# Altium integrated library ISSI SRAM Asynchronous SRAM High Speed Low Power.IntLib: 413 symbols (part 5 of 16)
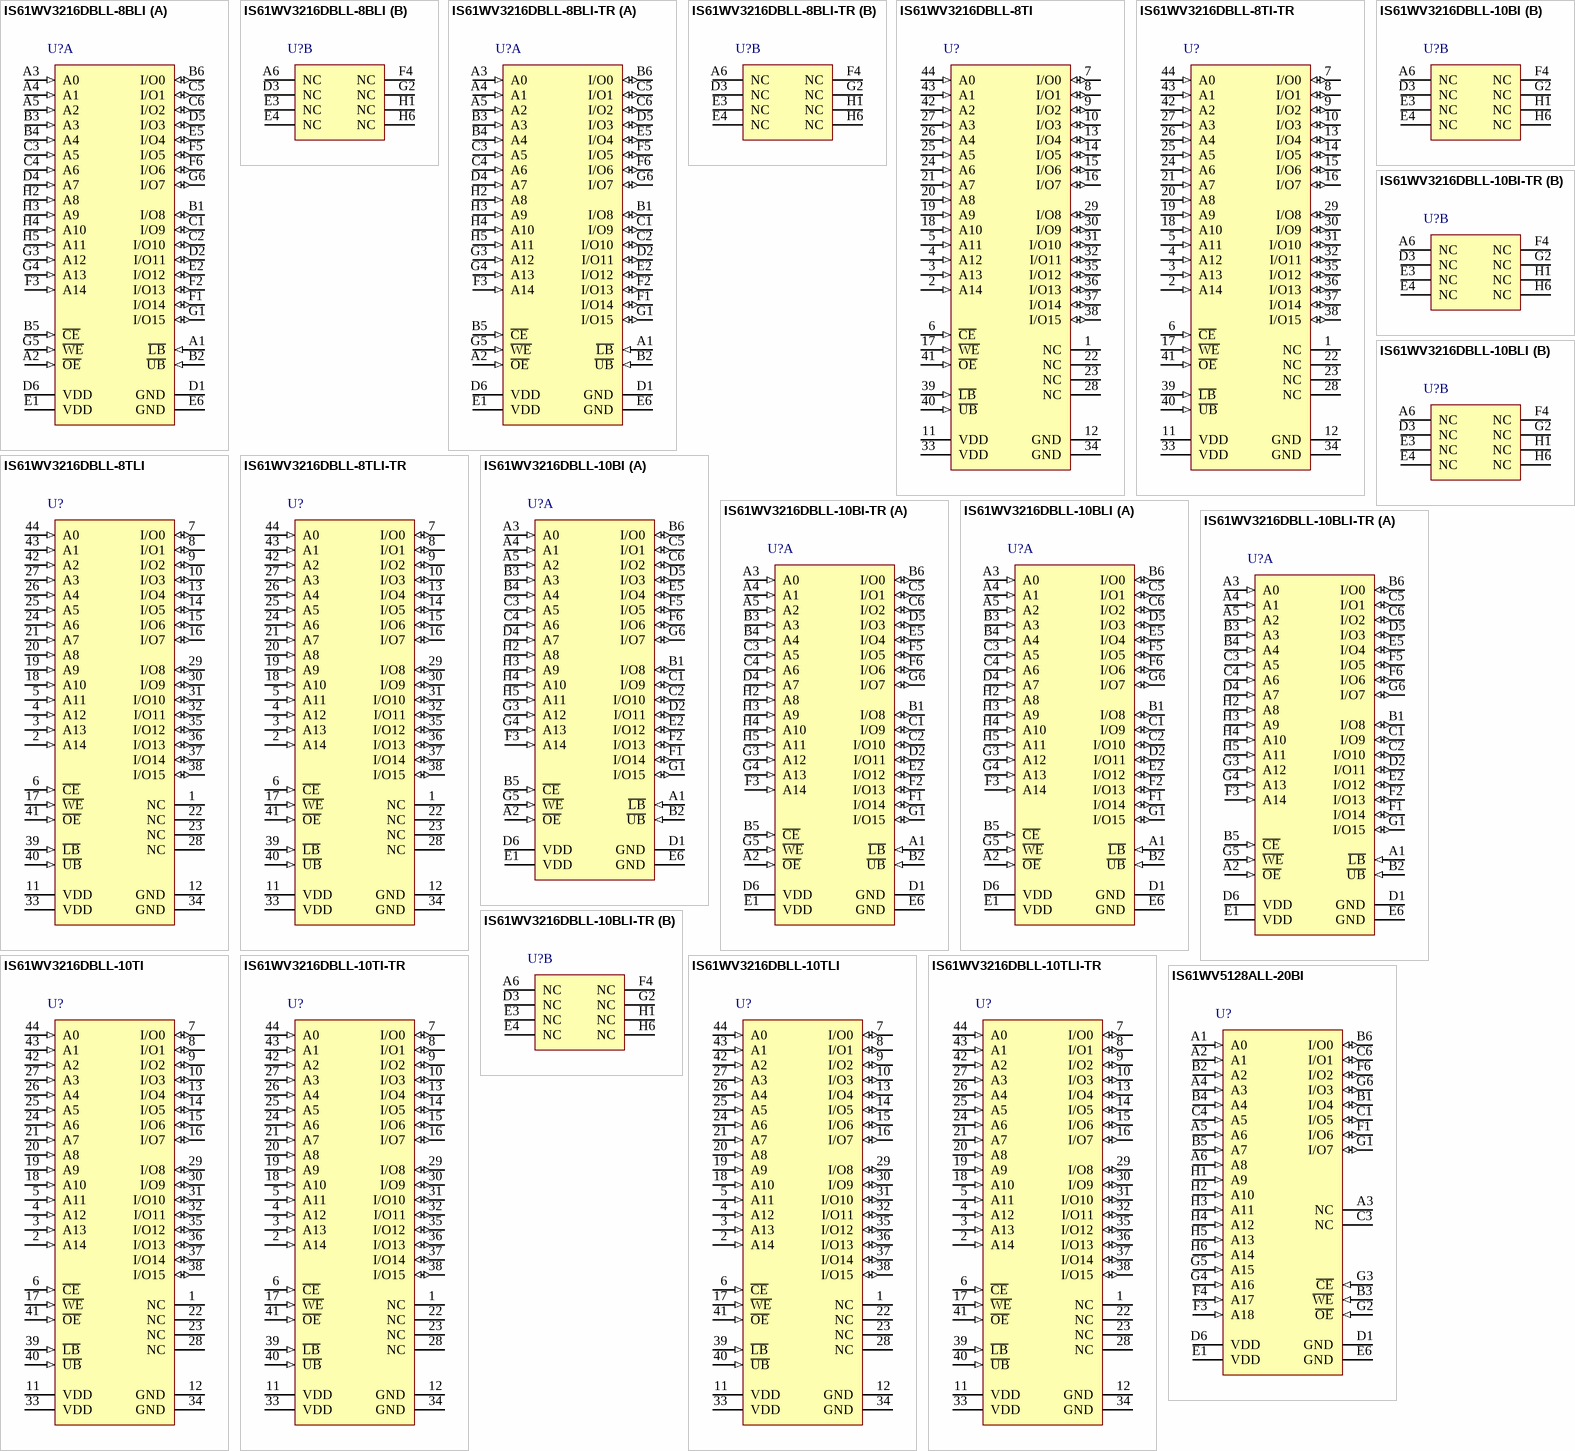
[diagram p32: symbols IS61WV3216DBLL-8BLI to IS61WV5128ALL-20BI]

## IS61WV3216DBLL-10TLI
designator U?
512 K High Speed Asynchronous CMOS SRAM, 32 K x 16, -40 to 85 degC, 44-Pin SOP (TSOP-2-44), Pb-Free; Manufacturer: Integrated Silicon Solution Inc (ISSI); PartNumber: IS61WV3216DBLL-10TLI; Density: 512K; Organization: 32K x 16; Packing: Tray / Tube; Speed (ns): 10
footprint ISSI-TSOP-2-44_N (SOP, 44-Leads, Body 18.5x10.3mm, Pitch 0.8mm, IPC Medium Density)
pins: 1 NC "No Connection", 2 A14 (in) "Address Input", 3 A13 (in) "Address Input", 4 A12 (in) "Address Input", 5 A11 (in) "Address Input", 6 ~{CE} (in) "Chip Enable Input", 7 I/O0 (io) "Data Input/Output", 8 I/O1 (io) "Data Input/Output", 9 I/O2 (io) "Data Input/Output", 10 I/O3 (io) "Data Input/Output", 11 VDD (power) "Power", 12 GND (power) "Ground", 13 I/O4 (io) "Data Input/Output", 14 I/O5 (io) "Data Input/Output", 15 I/O6 (io) "Data Input/Output", 16 I/O7 (io) "Data Input/Output", 17 ~{WE} (in) "Write Enable Input", 18 A10 (in) "Address Input", 19 A9 (in) "Address Input", 20 A8 (in) "Address Input", 21 A7 (in) "Address Input", 22 NC "No Connection", 23 NC "No Connection", 24 A6 (in) "Address Input", 25 A5 (in) "Address Input", 26 A4 (in) "Address Input", 27 A3 (in) "Address Input", 28 NC "No Connection", 29 I/O8 (io) "Data Input/Output", 30 I/O9 (io) "Data Input/Output", 31 I/O10 (io) "Data Input/Output", 32 I/O11 (io) "Data Input/Output", 33 VDD (power) "Power", 34 GND (power) "Ground", 35 I/O12 (io) "Data Input/Output", 36 I/O13 (io) "Data Input/Output", 37 I/O14 (io) "Data Input/Output", 38 I/O15 (io) "Data Input/Output", 39 ~{LB} (in) "Lower-byte Control (I/O0-I/O7)", 40 ~{UB} (in) "Upper-byte Control (I/O8-I/O15)", 41 ~{OE} (in) "Output Enable Input", 42 A2 (in) "Address Input", 43 A1 (in) "Address Input", 44 A0 (in) "Address Input"

## IS61WV3216DBLL-10TLI-TR
designator U?
512 K High Speed Asynchronous CMOS SRAM, 32 K x 16, -40 to 85 degC, 44-Pin SOP (TSOP-2-44), Pb-Free; Manufacturer: Integrated Silicon Solution Inc (ISSI); PartNumber: IS61WV3216DBLL-10TLI-TR; Density: 512K; Organization: 32K x 16; Packing: Tape & Reel; Speed (ns): 10
footprint ISSI-TSOP-2-44_N (SOP, 44-Leads, Body 18.5x10.3mm, Pitch 0.8mm, IPC Medium Density)
pins: 1 NC "No Connection", 2 A14 (in) "Address Input", 3 A13 (in) "Address Input", 4 A12 (in) "Address Input", 5 A11 (in) "Address Input", 6 ~{CE} (in) "Chip Enable Input", 7 I/O0 (io) "Data Input/Output", 8 I/O1 (io) "Data Input/Output", 9 I/O2 (io) "Data Input/Output", 10 I/O3 (io) "Data Input/Output", 11 VDD (power) "Power", 12 GND (power) "Ground", 13 I/O4 (io) "Data Input/Output", 14 I/O5 (io) "Data Input/Output", 15 I/O6 (io) "Data Input/Output", 16 I/O7 (io) "Data Input/Output", 17 ~{WE} (in) "Write Enable Input", 18 A10 (in) "Address Input", 19 A9 (in) "Address Input", 20 A8 (in) "Address Input", 21 A7 (in) "Address Input", 22 NC "No Connection", 23 NC "No Connection", 24 A6 (in) "Address Input", 25 A5 (in) "Address Input", 26 A4 (in) "Address Input", 27 A3 (in) "Address Input", 28 NC "No Connection", 29 I/O8 (io) "Data Input/Output", 30 I/O9 (io) "Data Input/Output", 31 I/O10 (io) "Data Input/Output", 32 I/O11 (io) "Data Input/Output", 33 VDD (power) "Power", 34 GND (power) "Ground", 35 I/O12 (io) "Data Input/Output", 36 I/O13 (io) "Data Input/Output", 37 I/O14 (io) "Data Input/Output", 38 I/O15 (io) "Data Input/Output", 39 ~{LB} (in) "Lower-byte Control (I/O0-I/O7)", 40 ~{UB} (in) "Upper-byte Control (I/O8-I/O15)", 41 ~{OE} (in) "Output Enable Input", 42 A2 (in) "Address Input", 43 A1 (in) "Address Input", 44 A0 (in) "Address Input"

## IS61WV5128ALL-20BI
designator U?
4 M High Speed Asynchronous CMOS SRAM, 512 K x 8, -40 to 85 degC, 36-Pin BGA (TF-BGA-36); Manufacturer: Integrated Silicon Solution Inc (ISSI); PartNumber: IS61WV5128ALL-20BI; Density: 4M; Organization: 512K x 8; Packing: Tray / Tube; Speed (ns): 20
footprint ISSI-TF-BGA-36-6000x8000DE (BGA, 36-Balls, Body 8x6mm, Pitch 0.75mm)
pins: A1 A0 (in) "Address Input", A2 A1 (in) "Address Input", A3 NC "No Connection", A4 A3 (in) "Address Input", A5 A6 (in) "Address Input", A6 A8 (in) "Address Input", B1 I/O4 (io) "Bidirectional Port", B2 A2 (in) "Address Input", B3 ~{WE} (in) "Write Enable Input", B4 A4 (in) "Address Input", B5 A7 (in) "Address Input", B6 I/O0 (io) "Bidirectional Port", C1 I/O5 (io) "Bidirectional Port", C3 NC "No Connection", C4 A5 (in) "Address Input", C6 I/O1 (io) "Bidirectional Port", D1 GND (power) "Ground", D6 VDD (power) "Power", E1 VDD (power) "Power", E6 GND (power) "Ground", F1 I/O6 (io) "Bidirectional Port", F3 A18 (in) "Address Input", F4 A17 (in) "Address Input", F6 I/O2 (io) "Bidirectional Port", G1 I/O7 (io) "Bidirectional Port", G2 ~{OE} (in) "Output Enable Input", G3 ~{CE} (in) "Chip Enable Input", G4 A16 (in) "Address Input", G5 A15 (in) "Address Input", G6 I/O3 (io) "Bidirectional Port", H1 A9 (in) "Address Input", H2 A10 (in) "Address Input", H3 A11 (in) "Address Input", H4 A12 (in) "Address Input", H5 A13 (in) "Address Input", H6 A14 (in) "Address Input"

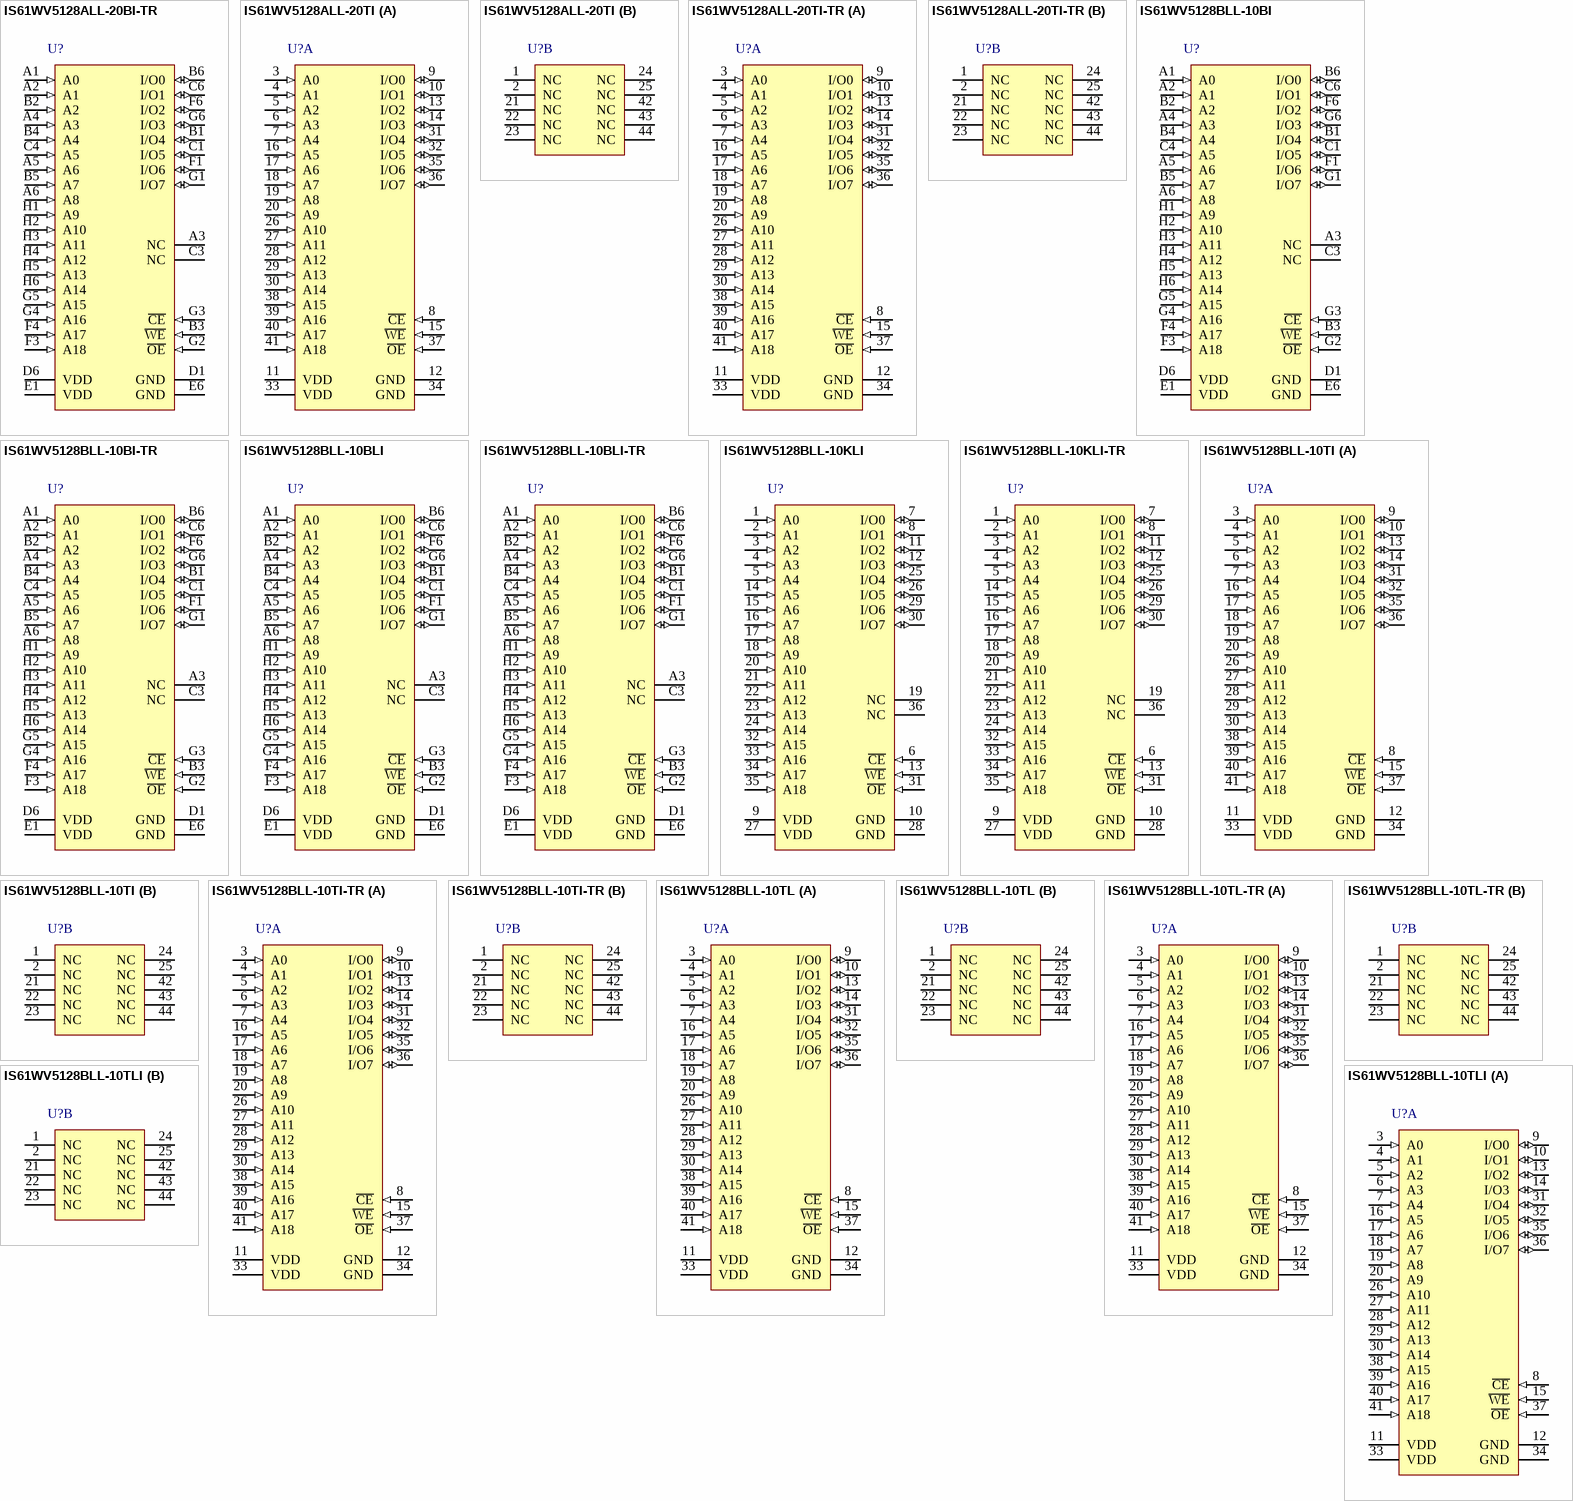
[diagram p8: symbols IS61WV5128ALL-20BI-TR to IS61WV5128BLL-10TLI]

## IS61WV5128ALL-20BI-TR
designator U?
4 M High Speed Asynchronous CMOS SRAM, 512 K x 8, -40 to 85 degC, 36-Pin BGA (TF-BGA-36); Manufacturer: Integrated Silicon Solution Inc (ISSI); PartNumber: IS61WV5128ALL-20BI-TR; Density: 4M; Organization: 512K x 8; Packing: Tape & Reel; Speed (ns): 20
footprint ISSI-TF-BGA-36-6000x8000DE (BGA, 36-Balls, Body 8x6mm, Pitch 0.75mm)
pins: A1 A0 (in) "Address Input", A2 A1 (in) "Address Input", A3 NC "No Connection", A4 A3 (in) "Address Input", A5 A6 (in) "Address Input", A6 A8 (in) "Address Input", B1 I/O4 (io) "Bidirectional Port", B2 A2 (in) "Address Input", B3 ~{WE} (in) "Write Enable Input", B4 A4 (in) "Address Input", B5 A7 (in) "Address Input", B6 I/O0 (io) "Bidirectional Port", C1 I/O5 (io) "Bidirectional Port", C3 NC "No Connection", C4 A5 (in) "Address Input", C6 I/O1 (io) "Bidirectional Port", D1 GND (power) "Ground", D6 VDD (power) "Power", E1 VDD (power) "Power", E6 GND (power) "Ground", F1 I/O6 (io) "Bidirectional Port", F3 A18 (in) "Address Input", F4 A17 (in) "Address Input", F6 I/O2 (io) "Bidirectional Port", G1 I/O7 (io) "Bidirectional Port", G2 ~{OE} (in) "Output Enable Input", G3 ~{CE} (in) "Chip Enable Input", G4 A16 (in) "Address Input", G5 A15 (in) "Address Input", G6 I/O3 (io) "Bidirectional Port", H1 A9 (in) "Address Input", H2 A10 (in) "Address Input", H3 A11 (in) "Address Input", H4 A12 (in) "Address Input", H5 A13 (in) "Address Input", H6 A14 (in) "Address Input"

## IS61WV5128ALL-20TI
designator U?
4 M High Speed Asynchronous CMOS SRAM, 512 K x 8, -40 to 85 degC, 44-Pin SOP (TSOP-2-44); Manufacturer: Integrated Silicon Solution Inc (ISSI); PartNumber: IS61WV5128ALL-20TI; Density: 4M; Organization: 512K x 8; Packing: Tray / Tube; Speed (ns): 20
footprint ISSI-TSOP-2-44_N (SOP, 44-Leads, Body 18.5x10.3mm, Pitch 0.8mm, IPC Medium Density)
part A pins: 3 A0 (in) "Address Input", 4 A1 (in) "Address Input", 5 A2 (in) "Address Input", 6 A3 (in) "Address Input", 7 A4 (in) "Address Input", 8 ~{CE} (in) "Chip Enable Input", 9 I/O0 (io) "Bidirectional Port", 10 I/O1 (io) "Bidirectional Port", 11 VDD (power) "Power", 12 GND (power) "Ground", 13 I/O2 (io) "Bidirectional Port", 14 I/O3 (io) "Bidirectional Port", 15 ~{WE} (in) "Write Enable Input", 16 A5 (in) "Address Input", 17 A6 (in) "Address Input", 18 A7 (in) "Address Input", 19 A8 (in) "Address Input", 20 A9 (in) "Address Input", 26 A10 (in) "Address Input", 27 A11 (in) "Address Input", 28 A12 (in) "Address Input", 29 A13 (in) "Address Input", 30 A14 (in) "Address Input", 31 I/O4 (io) "Bidirectional Port", 32 I/O5 (io) "Bidirectional Port", 33 VDD (power) "Power", 34 GND (power) "Ground", 35 I/O6 (io) "Bidirectional Port", 36 I/O7 (io) "Bidirectional Port", 37 ~{OE} (in) "Output Enable Input", 38 A15 (in) "Address Input", 39 A16 (in) "Address Input", 40 A17 (in) "Address Input", 41 A18 (in) "Address Input"
part B pins: 1 NC "No Connection", 2 NC "No Connection", 21 NC "No Connection", 22 NC "No Connection", 23 NC "No Connection", 24 NC "No Connection", 25 NC "No Connection", 42 NC "No Connection", 43 NC "No Connection", 44 NC "No Connection"

## IS61WV5128ALL-20TI-TR
designator U?
4 M High Speed Asynchronous CMOS SRAM, 512 K x 8, -40 to 85 degC, 44-Pin SOP (TSOP-2-44); Manufacturer: Integrated Silicon Solution Inc (ISSI); PartNumber: IS61WV5128ALL-20TI-TR; Density: 4M; Organization: 512K x 8; Packing: Tape & Reel; Speed (ns): 20
footprint ISSI-TSOP-2-44_N (SOP, 44-Leads, Body 18.5x10.3mm, Pitch 0.8mm, IPC Medium Density)
part A pins: 3 A0 (in) "Address Input", 4 A1 (in) "Address Input", 5 A2 (in) "Address Input", 6 A3 (in) "Address Input", 7 A4 (in) "Address Input", 8 ~{CE} (in) "Chip Enable Input", 9 I/O0 (io) "Bidirectional Port", 10 I/O1 (io) "Bidirectional Port", 11 VDD (power) "Power", 12 GND (power) "Ground", 13 I/O2 (io) "Bidirectional Port", 14 I/O3 (io) "Bidirectional Port", 15 ~{WE} (in) "Write Enable Input", 16 A5 (in) "Address Input", 17 A6 (in) "Address Input", 18 A7 (in) "Address Input", 19 A8 (in) "Address Input", 20 A9 (in) "Address Input", 26 A10 (in) "Address Input", 27 A11 (in) "Address Input", 28 A12 (in) "Address Input", 29 A13 (in) "Address Input", 30 A14 (in) "Address Input", 31 I/O4 (io) "Bidirectional Port", 32 I/O5 (io) "Bidirectional Port", 33 VDD (power) "Power", 34 GND (power) "Ground", 35 I/O6 (io) "Bidirectional Port", 36 I/O7 (io) "Bidirectional Port", 37 ~{OE} (in) "Output Enable Input", 38 A15 (in) "Address Input", 39 A16 (in) "Address Input", 40 A17 (in) "Address Input", 41 A18 (in) "Address Input"
part B pins: 1 NC "No Connection", 2 NC "No Connection", 21 NC "No Connection", 22 NC "No Connection", 23 NC "No Connection", 24 NC "No Connection", 25 NC "No Connection", 42 NC "No Connection", 43 NC "No Connection", 44 NC "No Connection"

## IS61WV5128BLL-10BI
designator U?
4 M High Speed Asynchronous CMOS SRAM, 512 K x 8, -40 to 85 degC, 36-Pin BGA (TF-BGA-36); Manufacturer: Integrated Silicon Solution Inc (ISSI); PartNumber: IS61WV5128BLL-10BI; Density: 4M; Organization: 512K x 8; Packing: Tray / Tube; Speed (ns): 10
footprint ISSI-TF-BGA-36-6000x8000DE (BGA, 36-Balls, Body 8x6mm, Pitch 0.75mm)
pins: A1 A0 (in) "Address Input", A2 A1 (in) "Address Input", A3 NC "No Connection", A4 A3 (in) "Address Input", A5 A6 (in) "Address Input", A6 A8 (in) "Address Input", B1 I/O4 (io) "Bidirectional Port", B2 A2 (in) "Address Input", B3 ~{WE} (in) "Write Enable Input", B4 A4 (in) "Address Input", B5 A7 (in) "Address Input", B6 I/O0 (io) "Bidirectional Port", C1 I/O5 (io) "Bidirectional Port", C3 NC "No Connection", C4 A5 (in) "Address Input", C6 I/O1 (io) "Bidirectional Port", D1 GND (power) "Ground", D6 VDD (power) "Power", E1 VDD (power) "Power", E6 GND (power) "Ground", F1 I/O6 (io) "Bidirectional Port", F3 A18 (in) "Address Input", F4 A17 (in) "Address Input", F6 I/O2 (io) "Bidirectional Port", G1 I/O7 (io) "Bidirectional Port", G2 ~{OE} (in) "Output Enable Input", G3 ~{CE} (in) "Chip Enable Input", G4 A16 (in) "Address Input", G5 A15 (in) "Address Input", G6 I/O3 (io) "Bidirectional Port", H1 A9 (in) "Address Input", H2 A10 (in) "Address Input", H3 A11 (in) "Address Input", H4 A12 (in) "Address Input", H5 A13 (in) "Address Input", H6 A14 (in) "Address Input"

## IS61WV5128BLL-10BI-TR
designator U?
4 M High Speed Asynchronous CMOS SRAM, 512 K x 8, -40 to 85 degC, 36-Pin BGA (TF-BGA-36); Manufacturer: Integrated Silicon Solution Inc (ISSI); PartNumber: IS61WV5128BLL-10BI-TR; Density: 4M; Organization: 512K x 8; Packing: Tape & Reel; Speed (ns): 10
footprint ISSI-TF-BGA-36-6000x8000DE (BGA, 36-Balls, Body 8x6mm, Pitch 0.75mm)
pins: A1 A0 (in) "Address Input", A2 A1 (in) "Address Input", A3 NC "No Connection", A4 A3 (in) "Address Input", A5 A6 (in) "Address Input", A6 A8 (in) "Address Input", B1 I/O4 (io) "Bidirectional Port", B2 A2 (in) "Address Input", B3 ~{WE} (in) "Write Enable Input", B4 A4 (in) "Address Input", B5 A7 (in) "Address Input", B6 I/O0 (io) "Bidirectional Port", C1 I/O5 (io) "Bidirectional Port", C3 NC "No Connection", C4 A5 (in) "Address Input", C6 I/O1 (io) "Bidirectional Port", D1 GND (power) "Ground", D6 VDD (power) "Power", E1 VDD (power) "Power", E6 GND (power) "Ground", F1 I/O6 (io) "Bidirectional Port", F3 A18 (in) "Address Input", F4 A17 (in) "Address Input", F6 I/O2 (io) "Bidirectional Port", G1 I/O7 (io) "Bidirectional Port", G2 ~{OE} (in) "Output Enable Input", G3 ~{CE} (in) "Chip Enable Input", G4 A16 (in) "Address Input", G5 A15 (in) "Address Input", G6 I/O3 (io) "Bidirectional Port", H1 A9 (in) "Address Input", H2 A10 (in) "Address Input", H3 A11 (in) "Address Input", H4 A12 (in) "Address Input", H5 A13 (in) "Address Input", H6 A14 (in) "Address Input"

## IS61WV5128BLL-10BLI
designator U?
4 M High Speed Asynchronous CMOS SRAM, 512 K x 8, -40 to 85 degC, 36-Pin BGA (TF-BGA-36), Pb-Free; Manufacturer: Integrated Silicon Solution Inc (ISSI); PartNumber: IS61WV5128BLL-10BLI; Density: 4M; Organization: 512K x 8; Packing: Tray / Tube; Speed (ns): 10
footprint ISSI-TF-BGA-36-6000x8000DE (BGA, 36-Balls, Body 8x6mm, Pitch 0.75mm)
pins: A1 A0 (in) "Address Input", A2 A1 (in) "Address Input", A3 NC "No Connection", A4 A3 (in) "Address Input", A5 A6 (in) "Address Input", A6 A8 (in) "Address Input", B1 I/O4 (io) "Bidirectional Port", B2 A2 (in) "Address Input", B3 ~{WE} (in) "Write Enable Input", B4 A4 (in) "Address Input", B5 A7 (in) "Address Input", B6 I/O0 (io) "Bidirectional Port", C1 I/O5 (io) "Bidirectional Port", C3 NC "No Connection", C4 A5 (in) "Address Input", C6 I/O1 (io) "Bidirectional Port", D1 GND (power) "Ground", D6 VDD (power) "Power", E1 VDD (power) "Power", E6 GND (power) "Ground", F1 I/O6 (io) "Bidirectional Port", F3 A18 (in) "Address Input", F4 A17 (in) "Address Input", F6 I/O2 (io) "Bidirectional Port", G1 I/O7 (io) "Bidirectional Port", G2 ~{OE} (in) "Output Enable Input", G3 ~{CE} (in) "Chip Enable Input", G4 A16 (in) "Address Input", G5 A15 (in) "Address Input", G6 I/O3 (io) "Bidirectional Port", H1 A9 (in) "Address Input", H2 A10 (in) "Address Input", H3 A11 (in) "Address Input", H4 A12 (in) "Address Input", H5 A13 (in) "Address Input", H6 A14 (in) "Address Input"

## IS61WV5128BLL-10BLI-TR
designator U?
4 M High Speed Asynchronous CMOS SRAM, 512 K x 8, -40 to 85 degC, 36-Pin BGA (TF-BGA-36), Pb-Free; Manufacturer: Integrated Silicon Solution Inc (ISSI); PartNumber: IS61WV5128BLL-10BLI-TR; Density: 4M; Organization: 512K x 8; Packing: Tape & Reel; Speed (ns): 10
footprint ISSI-TF-BGA-36-6000x8000DE (BGA, 36-Balls, Body 8x6mm, Pitch 0.75mm)
pins: A1 A0 (in) "Address Input", A2 A1 (in) "Address Input", A3 NC "No Connection", A4 A3 (in) "Address Input", A5 A6 (in) "Address Input", A6 A8 (in) "Address Input", B1 I/O4 (io) "Bidirectional Port", B2 A2 (in) "Address Input", B3 ~{WE} (in) "Write Enable Input", B4 A4 (in) "Address Input", B5 A7 (in) "Address Input", B6 I/O0 (io) "Bidirectional Port", C1 I/O5 (io) "Bidirectional Port", C3 NC "No Connection", C4 A5 (in) "Address Input", C6 I/O1 (io) "Bidirectional Port", D1 GND (power) "Ground", D6 VDD (power) "Power", E1 VDD (power) "Power", E6 GND (power) "Ground", F1 I/O6 (io) "Bidirectional Port", F3 A18 (in) "Address Input", F4 A17 (in) "Address Input", F6 I/O2 (io) "Bidirectional Port", G1 I/O7 (io) "Bidirectional Port", G2 ~{OE} (in) "Output Enable Input", G3 ~{CE} (in) "Chip Enable Input", G4 A16 (in) "Address Input", G5 A15 (in) "Address Input", G6 I/O3 (io) "Bidirectional Port", H1 A9 (in) "Address Input", H2 A10 (in) "Address Input", H3 A11 (in) "Address Input", H4 A12 (in) "Address Input", H5 A13 (in) "Address Input", H6 A14 (in) "Address Input"

## IS61WV5128BLL-10KLI
designator U?
4 M High Speed Asynchronous CMOS SRAM, 512 K x 8, -40 to 85 degC, 36-Pin SOJ (SOJ-36), Pb-Free; Manufacturer: Integrated Silicon Solution Inc (ISSI); PartNumber: IS61WV5128BLL-10KLI; Density: 4M; Organization: 512K x 8; Packing: Tray / Tube; Speed (ns): 10
footprint ISSI-SOJ-36_N (SOJ, 36-Leads, Body 23.62x10.29mm, Pitch 1.27mm, IPC Medium Density)
pins: 1 A0 (in) "Address Input", 2 A1 (in) "Address Input", 3 A2 (in) "Address Input", 4 A3 (in) "Address Input", 5 A4 (in) "Address Input", 6 ~{CE} (in) "Chip Enable Input", 7 I/O0 (io) "Bidirectional Port", 8 I/O1 (io) "Bidirectional Port", 9 VDD (power) "Power", 10 GND (power) "Ground", 11 I/O2 (io) "Bidirectional Port", 12 I/O3 (io) "Bidirectional Port", 13 ~{WE} (in) "Write Enable Input", 14 A5 (in) "Address Input", 15 A6 (in) "Address Input", 16 A7 (in) "Address Input", 17 A8 (in) "Address Input", 18 A9 (in) "Address Input", 19 NC "No Connection", 20 A10 (in) "Address Input", 21 A11 (in) "Address Input", 22 A12 (in) "Address Input", 23 A13 (in) "Address Input", 24 A14 (in) "Address Input", 25 I/O4 (io) "Bidirectional Port", 26 I/O5 (io) "Bidirectional Port", 27 VDD (power) "Power", 28 GND (power) "Ground", 29 I/O6 (io) "Bidirectional Port", 30 I/O7 (io) "Bidirectional Port", 31 ~{OE} (in) "Output Enable Input", 32 A15 (in) "Address Input", 33 A16 (in) "Address Input", 34 A17 (in) "Address Input", 35 A18 (in) "Address Input", 36 NC "No Connection"

## IS61WV5128BLL-10KLI-TR
designator U?
4 M High Speed Asynchronous CMOS SRAM, 512 K x 8, -40 to 85 degC, 36-Pin SOJ (SOJ-36), Pb-Free; Manufacturer: Integrated Silicon Solution Inc (ISSI); PartNumber: IS61WV5128BLL-10KLI-TR; Density: 4M; Organization: 512K x 8; Packing: Tape & Reel; Speed (ns): 10
footprint ISSI-SOJ-36_N (SOJ, 36-Leads, Body 23.62x10.29mm, Pitch 1.27mm, IPC Medium Density)
pins: 1 A0 (in) "Address Input", 2 A1 (in) "Address Input", 3 A2 (in) "Address Input", 4 A3 (in) "Address Input", 5 A4 (in) "Address Input", 6 ~{CE} (in) "Chip Enable Input", 7 I/O0 (io) "Bidirectional Port", 8 I/O1 (io) "Bidirectional Port", 9 VDD (power) "Power", 10 GND (power) "Ground", 11 I/O2 (io) "Bidirectional Port", 12 I/O3 (io) "Bidirectional Port", 13 ~{WE} (in) "Write Enable Input", 14 A5 (in) "Address Input", 15 A6 (in) "Address Input", 16 A7 (in) "Address Input", 17 A8 (in) "Address Input", 18 A9 (in) "Address Input", 19 NC "No Connection", 20 A10 (in) "Address Input", 21 A11 (in) "Address Input", 22 A12 (in) "Address Input", 23 A13 (in) "Address Input", 24 A14 (in) "Address Input", 25 I/O4 (io) "Bidirectional Port", 26 I/O5 (io) "Bidirectional Port", 27 VDD (power) "Power", 28 GND (power) "Ground", 29 I/O6 (io) "Bidirectional Port", 30 I/O7 (io) "Bidirectional Port", 31 ~{OE} (in) "Output Enable Input", 32 A15 (in) "Address Input", 33 A16 (in) "Address Input", 34 A17 (in) "Address Input", 35 A18 (in) "Address Input", 36 NC "No Connection"

## IS61WV5128BLL-10TI
designator U?
4 M High Speed Asynchronous CMOS SRAM, 512 K x 8, -40 to 85 degC, 44-Pin SOP (TSOP-2-44); Manufacturer: Integrated Silicon Solution Inc (ISSI); PartNumber: IS61WV5128BLL-10TI; Density: 4M; Organization: 512K x 8; Packing: Tray / Tube; Speed (ns): 10
footprint ISSI-TSOP-2-44_N (SOP, 44-Leads, Body 18.5x10.3mm, Pitch 0.8mm, IPC Medium Density)
part A pins: 3 A0 (in) "Address Input", 4 A1 (in) "Address Input", 5 A2 (in) "Address Input", 6 A3 (in) "Address Input", 7 A4 (in) "Address Input", 8 ~{CE} (in) "Chip Enable Input", 9 I/O0 (io) "Bidirectional Port", 10 I/O1 (io) "Bidirectional Port", 11 VDD (power) "Power", 12 GND (power) "Ground", 13 I/O2 (io) "Bidirectional Port", 14 I/O3 (io) "Bidirectional Port", 15 ~{WE} (in) "Write Enable Input", 16 A5 (in) "Address Input", 17 A6 (in) "Address Input", 18 A7 (in) "Address Input", 19 A8 (in) "Address Input", 20 A9 (in) "Address Input", 26 A10 (in) "Address Input", 27 A11 (in) "Address Input", 28 A12 (in) "Address Input", 29 A13 (in) "Address Input", 30 A14 (in) "Address Input", 31 I/O4 (io) "Bidirectional Port", 32 I/O5 (io) "Bidirectional Port", 33 VDD (power) "Power", 34 GND (power) "Ground", 35 I/O6 (io) "Bidirectional Port", 36 I/O7 (io) "Bidirectional Port", 37 ~{OE} (in) "Output Enable Input", 38 A15 (in) "Address Input", 39 A16 (in) "Address Input", 40 A17 (in) "Address Input", 41 A18 (in) "Address Input"
part B pins: 1 NC "No Connection", 2 NC "No Connection", 21 NC "No Connection", 22 NC "No Connection", 23 NC "No Connection", 24 NC "No Connection", 25 NC "No Connection", 42 NC "No Connection", 43 NC "No Connection", 44 NC "No Connection"

## IS61WV5128BLL-10TI-TR
designator U?
4 M High Speed Asynchronous CMOS SRAM, 512 K x 8, -40 to 85 degC, 44-Pin SOP (TSOP-2-44); Manufacturer: Integrated Silicon Solution Inc (ISSI); PartNumber: IS61WV5128BLL-10TI-TR; Density: 4M; Organization: 512K x 8; Packing: Tape & Reel; Speed (ns): 10
footprint ISSI-TSOP-2-44_N (SOP, 44-Leads, Body 18.5x10.3mm, Pitch 0.8mm, IPC Medium Density)
part A pins: 3 A0 (in) "Address Input", 4 A1 (in) "Address Input", 5 A2 (in) "Address Input", 6 A3 (in) "Address Input", 7 A4 (in) "Address Input", 8 ~{CE} (in) "Chip Enable Input", 9 I/O0 (io) "Bidirectional Port", 10 I/O1 (io) "Bidirectional Port", 11 VDD (power) "Power", 12 GND (power) "Ground", 13 I/O2 (io) "Bidirectional Port", 14 I/O3 (io) "Bidirectional Port", 15 ~{WE} (in) "Write Enable Input", 16 A5 (in) "Address Input", 17 A6 (in) "Address Input", 18 A7 (in) "Address Input", 19 A8 (in) "Address Input", 20 A9 (in) "Address Input", 26 A10 (in) "Address Input", 27 A11 (in) "Address Input", 28 A12 (in) "Address Input", 29 A13 (in) "Address Input", 30 A14 (in) "Address Input", 31 I/O4 (io) "Bidirectional Port", 32 I/O5 (io) "Bidirectional Port", 33 VDD (power) "Power", 34 GND (power) "Ground", 35 I/O6 (io) "Bidirectional Port", 36 I/O7 (io) "Bidirectional Port", 37 ~{OE} (in) "Output Enable Input", 38 A15 (in) "Address Input", 39 A16 (in) "Address Input", 40 A17 (in) "Address Input", 41 A18 (in) "Address Input"
part B pins: 1 NC "No Connection", 2 NC "No Connection", 21 NC "No Connection", 22 NC "No Connection", 23 NC "No Connection", 24 NC "No Connection", 25 NC "No Connection", 42 NC "No Connection", 43 NC "No Connection", 44 NC "No Connection"

## IS61WV5128BLL-10TL
designator U?
4 M High Speed Asynchronous CMOS SRAM, 512 K x 8, 0 to 70 degC, 44-Pin SOP (TSOP-2-44), Pb-Free; Manufacturer: Integrated Silicon Solution Inc (ISSI); PartNumber: IS61WV5128BLL-10TL; Density: 4M; Organization: 512K x 8; Packing: Tray / Tube; Speed (ns): 10
footprint ISSI-TSOP-2-44_N (SOP, 44-Leads, Body 18.5x10.3mm, Pitch 0.8mm, IPC Medium Density)
part A pins: 3 A0 (in) "Address Input", 4 A1 (in) "Address Input", 5 A2 (in) "Address Input", 6 A3 (in) "Address Input", 7 A4 (in) "Address Input", 8 ~{CE} (in) "Chip Enable Input", 9 I/O0 (io) "Bidirectional Port", 10 I/O1 (io) "Bidirectional Port", 11 VDD (power) "Power", 12 GND (power) "Ground", 13 I/O2 (io) "Bidirectional Port", 14 I/O3 (io) "Bidirectional Port", 15 ~{WE} (in) "Write Enable Input", 16 A5 (in) "Address Input", 17 A6 (in) "Address Input", 18 A7 (in) "Address Input", 19 A8 (in) "Address Input", 20 A9 (in) "Address Input", 26 A10 (in) "Address Input", 27 A11 (in) "Address Input", 28 A12 (in) "Address Input", 29 A13 (in) "Address Input", 30 A14 (in) "Address Input", 31 I/O4 (io) "Bidirectional Port", 32 I/O5 (io) "Bidirectional Port", 33 VDD (power) "Power", 34 GND (power) "Ground", 35 I/O6 (io) "Bidirectional Port", 36 I/O7 (io) "Bidirectional Port", 37 ~{OE} (in) "Output Enable Input", 38 A15 (in) "Address Input", 39 A16 (in) "Address Input", 40 A17 (in) "Address Input", 41 A18 (in) "Address Input"
part B pins: 1 NC "No Connection", 2 NC "No Connection", 21 NC "No Connection", 22 NC "No Connection", 23 NC "No Connection", 24 NC "No Connection", 25 NC "No Connection", 42 NC "No Connection", 43 NC "No Connection", 44 NC "No Connection"

## IS61WV5128BLL-10TL-TR
designator U?
4 M High Speed Asynchronous CMOS SRAM, 512 K x 8, 0 to 70 degC, 44-Pin SOP (TSOP-2-44), Pb-Free; Manufacturer: Integrated Silicon Solution Inc (ISSI); PartNumber: IS61WV5128BLL-10TL-TR; Density: 4M; Organization: 512K x 8; Packing: Tape & Reel; Speed (ns): 10
footprint ISSI-TSOP-2-44_N (SOP, 44-Leads, Body 18.5x10.3mm, Pitch 0.8mm, IPC Medium Density)
part A pins: 3 A0 (in) "Address Input", 4 A1 (in) "Address Input", 5 A2 (in) "Address Input", 6 A3 (in) "Address Input", 7 A4 (in) "Address Input", 8 ~{CE} (in) "Chip Enable Input", 9 I/O0 (io) "Bidirectional Port", 10 I/O1 (io) "Bidirectional Port", 11 VDD (power) "Power", 12 GND (power) "Ground", 13 I/O2 (io) "Bidirectional Port", 14 I/O3 (io) "Bidirectional Port", 15 ~{WE} (in) "Write Enable Input", 16 A5 (in) "Address Input", 17 A6 (in) "Address Input", 18 A7 (in) "Address Input", 19 A8 (in) "Address Input", 20 A9 (in) "Address Input", 26 A10 (in) "Address Input", 27 A11 (in) "Address Input", 28 A12 (in) "Address Input", 29 A13 (in) "Address Input", 30 A14 (in) "Address Input", 31 I/O4 (io) "Bidirectional Port", 32 I/O5 (io) "Bidirectional Port", 33 VDD (power) "Power", 34 GND (power) "Ground", 35 I/O6 (io) "Bidirectional Port", 36 I/O7 (io) "Bidirectional Port", 37 ~{OE} (in) "Output Enable Input", 38 A15 (in) "Address Input", 39 A16 (in) "Address Input", 40 A17 (in) "Address Input", 41 A18 (in) "Address Input"
part B pins: 1 NC "No Connection", 2 NC "No Connection", 21 NC "No Connection", 22 NC "No Connection", 23 NC "No Connection", 24 NC "No Connection", 25 NC "No Connection", 42 NC "No Connection", 43 NC "No Connection", 44 NC "No Connection"

## IS61WV5128BLL-10TLI
designator U?
4 M High Speed Asynchronous CMOS SRAM, 512 K x 8, -40 to 85 degC, 44-Pin SOP (TSOP-2-44), Pb-Free; Manufacturer: Integrated Silicon Solution Inc (ISSI); PartNumber: IS61WV5128BLL-10TLI; Density: 4M; Organization: 512K x 8; Packing: Tray / Tube; Speed (ns): 10
footprint ISSI-TSOP-2-44_N (SOP, 44-Leads, Body 18.5x10.3mm, Pitch 0.8mm, IPC Medium Density)
part A pins: 3 A0 (in) "Address Input", 4 A1 (in) "Address Input", 5 A2 (in) "Address Input", 6 A3 (in) "Address Input", 7 A4 (in) "Address Input", 8 ~{CE} (in) "Chip Enable Input", 9 I/O0 (io) "Bidirectional Port", 10 I/O1 (io) "Bidirectional Port", 11 VDD (power) "Power", 12 GND (power) "Ground", 13 I/O2 (io) "Bidirectional Port", 14 I/O3 (io) "Bidirectional Port", 15 ~{WE} (in) "Write Enable Input", 16 A5 (in) "Address Input", 17 A6 (in) "Address Input", 18 A7 (in) "Address Input", 19 A8 (in) "Address Input", 20 A9 (in) "Address Input", 26 A10 (in) "Address Input", 27 A11 (in) "Address Input", 28 A12 (in) "Address Input", 29 A13 (in) "Address Input", 30 A14 (in) "Address Input", 31 I/O4 (io) "Bidirectional Port", 32 I/O5 (io) "Bidirectional Port", 33 VDD (power) "Power", 34 GND (power) "Ground", 35 I/O6 (io) "Bidirectional Port", 36 I/O7 (io) "Bidirectional Port", 37 ~{OE} (in) "Output Enable Input", 38 A15 (in) "Address Input", 39 A16 (in) "Address Input", 40 A17 (in) "Address Input", 41 A18 (in) "Address Input"
part B pins: 1 NC "No Connection", 2 NC "No Connection", 21 NC "No Connection", 22 NC "No Connection", 23 NC "No Connection", 24 NC "No Connection", 25 NC "No Connection", 42 NC "No Connection", 43 NC "No Connection", 44 NC "No Connection"

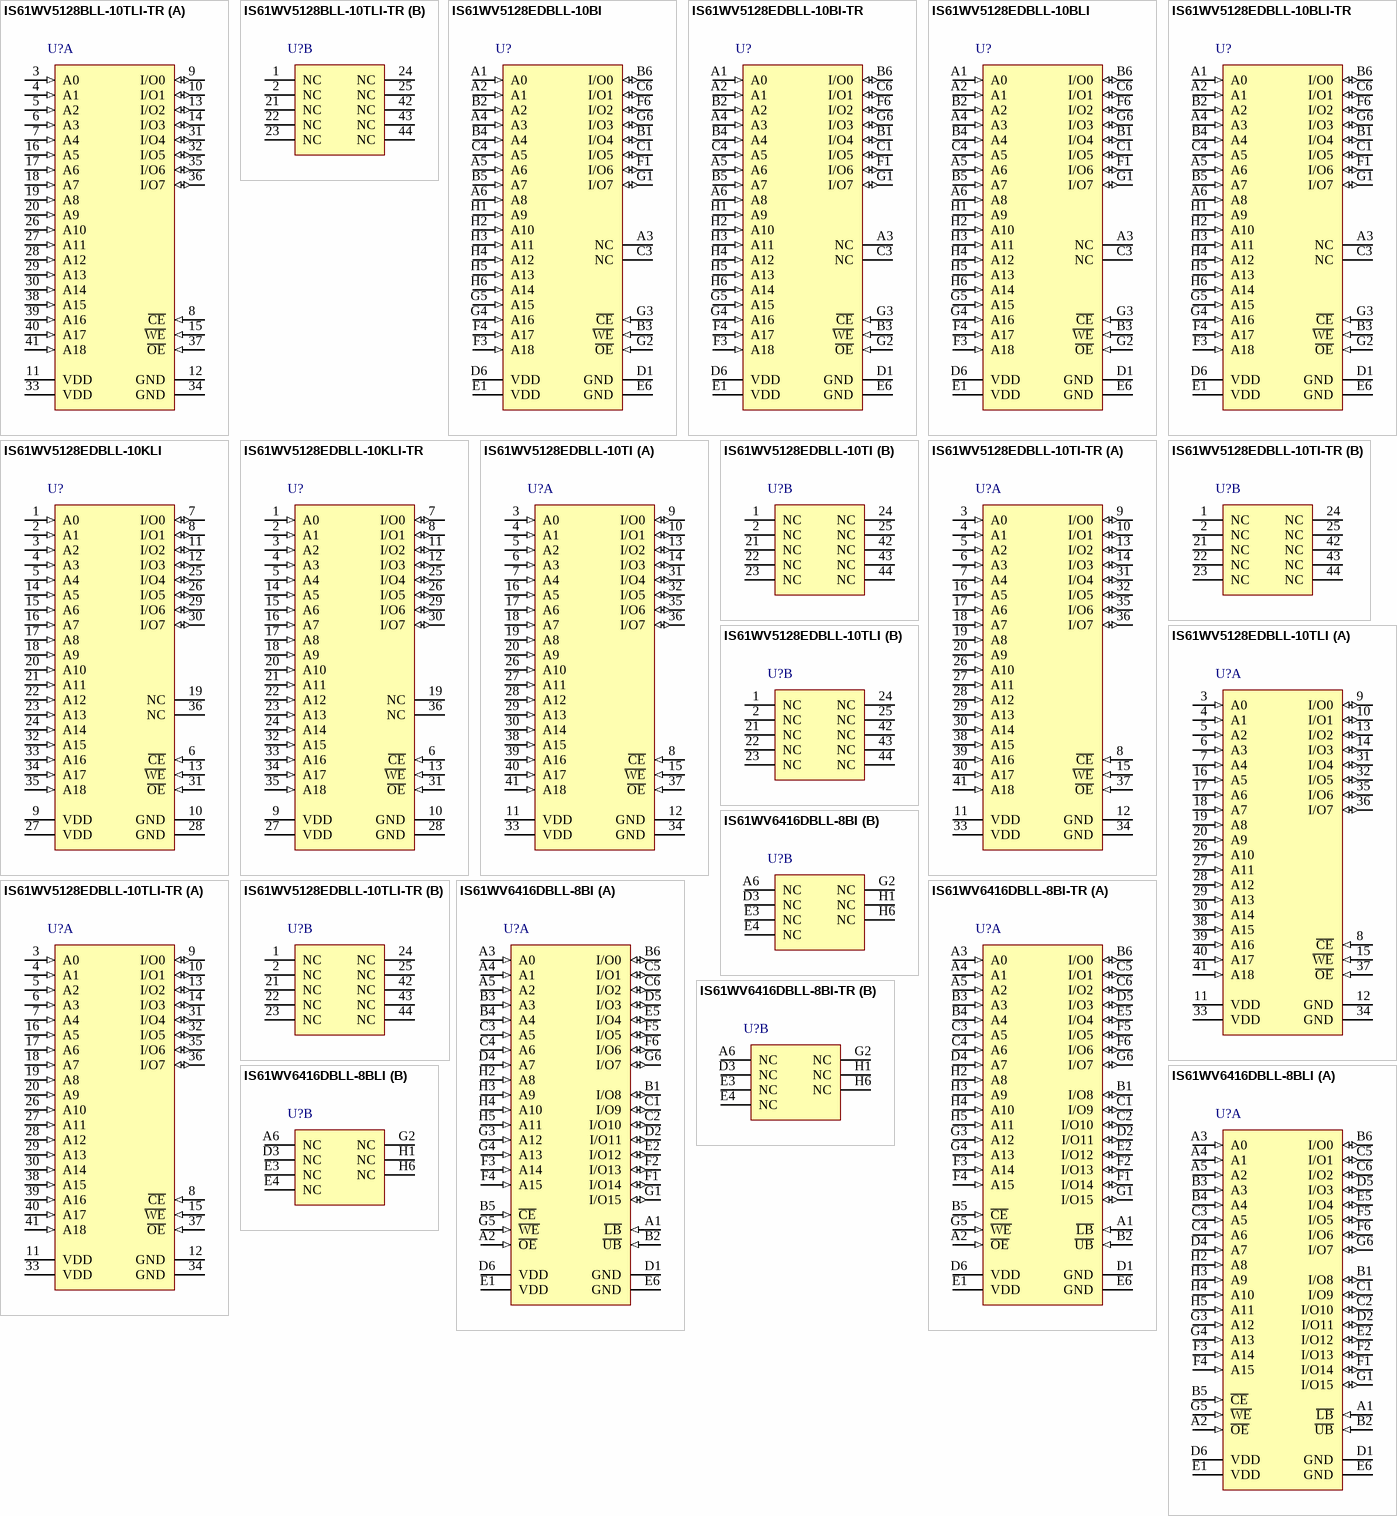
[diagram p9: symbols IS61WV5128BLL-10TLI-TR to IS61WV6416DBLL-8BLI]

## IS61WV5128BLL-10TLI-TR
designator U?
4 M High Speed Asynchronous CMOS SRAM, 512 K x 8, -40 to 85 degC, 44-Pin SOP (TSOP-2-44), Pb-Free; Manufacturer: Integrated Silicon Solution Inc (ISSI); PartNumber: IS61WV5128BLL-10TLI-TR; Density: 4M; Organization: 512K x 8; Packing: Tape & Reel; Speed (ns): 10
footprint ISSI-TSOP-2-44_N (SOP, 44-Leads, Body 18.5x10.3mm, Pitch 0.8mm, IPC Medium Density)
part A pins: 3 A0 (in) "Address Input", 4 A1 (in) "Address Input", 5 A2 (in) "Address Input", 6 A3 (in) "Address Input", 7 A4 (in) "Address Input", 8 ~{CE} (in) "Chip Enable Input", 9 I/O0 (io) "Bidirectional Port", 10 I/O1 (io) "Bidirectional Port", 11 VDD (power) "Power", 12 GND (power) "Ground", 13 I/O2 (io) "Bidirectional Port", 14 I/O3 (io) "Bidirectional Port", 15 ~{WE} (in) "Write Enable Input", 16 A5 (in) "Address Input", 17 A6 (in) "Address Input", 18 A7 (in) "Address Input", 19 A8 (in) "Address Input", 20 A9 (in) "Address Input", 26 A10 (in) "Address Input", 27 A11 (in) "Address Input", 28 A12 (in) "Address Input", 29 A13 (in) "Address Input", 30 A14 (in) "Address Input", 31 I/O4 (io) "Bidirectional Port", 32 I/O5 (io) "Bidirectional Port", 33 VDD (power) "Power", 34 GND (power) "Ground", 35 I/O6 (io) "Bidirectional Port", 36 I/O7 (io) "Bidirectional Port", 37 ~{OE} (in) "Output Enable Input", 38 A15 (in) "Address Input", 39 A16 (in) "Address Input", 40 A17 (in) "Address Input", 41 A18 (in) "Address Input"
part B pins: 1 NC "No Connection", 2 NC "No Connection", 21 NC "No Connection", 22 NC "No Connection", 23 NC "No Connection", 24 NC "No Connection", 25 NC "No Connection", 42 NC "No Connection", 43 NC "No Connection", 44 NC "No Connection"

## IS61WV5128EDBLL-10BI
designator U?
4 M High Speed Asynchronous CMOS SRAM with ECC, 512 K x 8, -40 to 85 degC, 36-Pin BGA (TF-BGA-36); Manufacturer: Integrated Silicon Solution Inc (ISSI); PartNumber: IS61WV5128EDBLL-10BI; Density: 4M; Organization: 512K x 8; Packing: Tray / Tube; Speed (ns): 10
footprint ISSI-TF-BGA-36-6000x8000DE (BGA, 36-Balls, Body 8x6mm, Pitch 0.75mm)
pins: A1 A0 (in) "Address Input", A2 A1 (in) "Address Input", A3 NC "No Connection", A4 A3 (in) "Address Input", A5 A6 (in) "Address Input", A6 A8 (in) "Address Input", B1 I/O4 (io) "Bidirectional Port", B2 A2 (in) "Address Input", B3 ~{WE} (in) "Write Enable Input", B4 A4 (in) "Address Input", B5 A7 (in) "Address Input", B6 I/O0 (io) "Bidirectional Port", C1 I/O5 (io) "Bidirectional Port", C3 NC "No Connection", C4 A5 (in) "Address Input", C6 I/O1 (io) "Bidirectional Port", D1 GND (power) "Ground", D6 VDD (power) "Power", E1 VDD (power) "Power", E6 GND (power) "Ground", F1 I/O6 (io) "Bidirectional Port", F3 A18 (in) "Address Input", F4 A17 (in) "Address Input", F6 I/O2 (io) "Bidirectional Port", G1 I/O7 (io) "Bidirectional Port", G2 ~{OE} (in) "Output Enable Input", G3 ~{CE} (in) "Chip Enable Input", G4 A16 (in) "Address Input", G5 A15 (in) "Address Input", G6 I/O3 (io) "Bidirectional Port", H1 A9 (in) "Address Input", H2 A10 (in) "Address Input", H3 A11 (in) "Address Input", H4 A12 (in) "Address Input", H5 A13 (in) "Address Input", H6 A14 (in) "Address Input"

## IS61WV5128EDBLL-10BI-TR
designator U?
4 M High Speed Asynchronous CMOS SRAM with ECC, 512 K x 8, -40 to 85 degC, 36-Pin BGA (TF-BGA-36); Manufacturer: Integrated Silicon Solution Inc (ISSI); PartNumber: IS61WV5128EDBLL-10BI-TR; Density: 4M; Organization: 512K x 8; Packing: Tape & Reel; Speed (ns): 10
footprint ISSI-TF-BGA-36-6000x8000DE (BGA, 36-Balls, Body 8x6mm, Pitch 0.75mm)
pins: A1 A0 (in) "Address Input", A2 A1 (in) "Address Input", A3 NC "No Connection", A4 A3 (in) "Address Input", A5 A6 (in) "Address Input", A6 A8 (in) "Address Input", B1 I/O4 (io) "Bidirectional Port", B2 A2 (in) "Address Input", B3 ~{WE} (in) "Write Enable Input", B4 A4 (in) "Address Input", B5 A7 (in) "Address Input", B6 I/O0 (io) "Bidirectional Port", C1 I/O5 (io) "Bidirectional Port", C3 NC "No Connection", C4 A5 (in) "Address Input", C6 I/O1 (io) "Bidirectional Port", D1 GND (power) "Ground", D6 VDD (power) "Power", E1 VDD (power) "Power", E6 GND (power) "Ground", F1 I/O6 (io) "Bidirectional Port", F3 A18 (in) "Address Input", F4 A17 (in) "Address Input", F6 I/O2 (io) "Bidirectional Port", G1 I/O7 (io) "Bidirectional Port", G2 ~{OE} (in) "Output Enable Input", G3 ~{CE} (in) "Chip Enable Input", G4 A16 (in) "Address Input", G5 A15 (in) "Address Input", G6 I/O3 (io) "Bidirectional Port", H1 A9 (in) "Address Input", H2 A10 (in) "Address Input", H3 A11 (in) "Address Input", H4 A12 (in) "Address Input", H5 A13 (in) "Address Input", H6 A14 (in) "Address Input"

## IS61WV5128EDBLL-10BLI
designator U?
4 M High Speed Asynchronous CMOS SRAM with ECC, 512 K x 8, -40 to 85 degC, 36-Pin BGA (TF-BGA-36), Pb-Free; Manufacturer: Integrated Silicon Solution Inc (ISSI); PartNumber: IS61WV5128EDBLL-10BLI; Density: 4M; Organization: 512K x 8; Packing: Tray / Tube; Speed (ns): 10
footprint ISSI-TF-BGA-36-6000x8000DE (BGA, 36-Balls, Body 8x6mm, Pitch 0.75mm)
pins: A1 A0 (in) "Address Input", A2 A1 (in) "Address Input", A3 NC "No Connection", A4 A3 (in) "Address Input", A5 A6 (in) "Address Input", A6 A8 (in) "Address Input", B1 I/O4 (io) "Bidirectional Port", B2 A2 (in) "Address Input", B3 ~{WE} (in) "Write Enable Input", B4 A4 (in) "Address Input", B5 A7 (in) "Address Input", B6 I/O0 (io) "Bidirectional Port", C1 I/O5 (io) "Bidirectional Port", C3 NC "No Connection", C4 A5 (in) "Address Input", C6 I/O1 (io) "Bidirectional Port", D1 GND (power) "Ground", D6 VDD (power) "Power", E1 VDD (power) "Power", E6 GND (power) "Ground", F1 I/O6 (io) "Bidirectional Port", F3 A18 (in) "Address Input", F4 A17 (in) "Address Input", F6 I/O2 (io) "Bidirectional Port", G1 I/O7 (io) "Bidirectional Port", G2 ~{OE} (in) "Output Enable Input", G3 ~{CE} (in) "Chip Enable Input", G4 A16 (in) "Address Input", G5 A15 (in) "Address Input", G6 I/O3 (io) "Bidirectional Port", H1 A9 (in) "Address Input", H2 A10 (in) "Address Input", H3 A11 (in) "Address Input", H4 A12 (in) "Address Input", H5 A13 (in) "Address Input", H6 A14 (in) "Address Input"

## IS61WV5128EDBLL-10BLI-TR
designator U?
4 M High Speed Asynchronous CMOS SRAM with ECC, 512 K x 8, -40 to 85 degC, 36-Pin BGA (TF-BGA-36), Pb-Free; Manufacturer: Integrated Silicon Solution Inc (ISSI); PartNumber: IS61WV5128EDBLL-10BLI-TR; Density: 4M; Organization: 512K x 8; Packing: Tape & Reel; Speed (ns): 10
footprint ISSI-TF-BGA-36-6000x8000DE (BGA, 36-Balls, Body 8x6mm, Pitch 0.75mm)
pins: A1 A0 (in) "Address Input", A2 A1 (in) "Address Input", A3 NC "No Connection", A4 A3 (in) "Address Input", A5 A6 (in) "Address Input", A6 A8 (in) "Address Input", B1 I/O4 (io) "Bidirectional Port", B2 A2 (in) "Address Input", B3 ~{WE} (in) "Write Enable Input", B4 A4 (in) "Address Input", B5 A7 (in) "Address Input", B6 I/O0 (io) "Bidirectional Port", C1 I/O5 (io) "Bidirectional Port", C3 NC "No Connection", C4 A5 (in) "Address Input", C6 I/O1 (io) "Bidirectional Port", D1 GND (power) "Ground", D6 VDD (power) "Power", E1 VDD (power) "Power", E6 GND (power) "Ground", F1 I/O6 (io) "Bidirectional Port", F3 A18 (in) "Address Input", F4 A17 (in) "Address Input", F6 I/O2 (io) "Bidirectional Port", G1 I/O7 (io) "Bidirectional Port", G2 ~{OE} (in) "Output Enable Input", G3 ~{CE} (in) "Chip Enable Input", G4 A16 (in) "Address Input", G5 A15 (in) "Address Input", G6 I/O3 (io) "Bidirectional Port", H1 A9 (in) "Address Input", H2 A10 (in) "Address Input", H3 A11 (in) "Address Input", H4 A12 (in) "Address Input", H5 A13 (in) "Address Input", H6 A14 (in) "Address Input"

## IS61WV5128EDBLL-10KLI
designator U?
4 M High Speed Asynchronous CMOS SRAM with ECC, 512 K x 8, -40 to 85 degC, 36-Pin SOJ (SOJ-36), Pb-Free; Manufacturer: Integrated Silicon Solution Inc (ISSI); PartNumber: IS61WV5128EDBLL-10KLI; Density: 4M; Organization: 512K x 8; Packing: Tray / Tube; Speed (ns): 10
footprint ISSI-SOJ-36_N (SOJ, 36-Leads, Body 23.62x10.29mm, Pitch 1.27mm, IPC Medium Density)
pins: 1 A0 (in) "Address Input", 2 A1 (in) "Address Input", 3 A2 (in) "Address Input", 4 A3 (in) "Address Input", 5 A4 (in) "Address Input", 6 ~{CE} (in) "Chip Enable Input", 7 I/O0 (io) "Bidirectional Port", 8 I/O1 (io) "Bidirectional Port", 9 VDD (power) "Power", 10 GND (power) "Ground", 11 I/O2 (io) "Bidirectional Port", 12 I/O3 (io) "Bidirectional Port", 13 ~{WE} (in) "Write Enable Input", 14 A5 (in) "Address Input", 15 A6 (in) "Address Input", 16 A7 (in) "Address Input", 17 A8 (in) "Address Input", 18 A9 (in) "Address Input", 19 NC "No Connection", 20 A10 (in) "Address Input", 21 A11 (in) "Address Input", 22 A12 (in) "Address Input", 23 A13 (in) "Address Input", 24 A14 (in) "Address Input", 25 I/O4 (io) "Bidirectional Port", 26 I/O5 (io) "Bidirectional Port", 27 VDD (power) "Power", 28 GND (power) "Ground", 29 I/O6 (io) "Bidirectional Port", 30 I/O7 (io) "Bidirectional Port", 31 ~{OE} (in) "Output Enable Input", 32 A15 (in) "Address Input", 33 A16 (in) "Address Input", 34 A17 (in) "Address Input", 35 A18 (in) "Address Input", 36 NC "No Connection"

## IS61WV5128EDBLL-10KLI-TR
designator U?
4 M High Speed Asynchronous CMOS SRAM with ECC, 512 K x 8, -40 to 85 degC, 36-Pin SOJ (SOJ-36), Pb-Free; Manufacturer: Integrated Silicon Solution Inc (ISSI); PartNumber: IS61WV5128EDBLL-10KLI-TR; Density: 4M; Organization: 512K x 8; Packing: Tape & Reel; Speed (ns): 10
footprint ISSI-SOJ-36_N (SOJ, 36-Leads, Body 23.62x10.29mm, Pitch 1.27mm, IPC Medium Density)
pins: 1 A0 (in) "Address Input", 2 A1 (in) "Address Input", 3 A2 (in) "Address Input", 4 A3 (in) "Address Input", 5 A4 (in) "Address Input", 6 ~{CE} (in) "Chip Enable Input", 7 I/O0 (io) "Bidirectional Port", 8 I/O1 (io) "Bidirectional Port", 9 VDD (power) "Power", 10 GND (power) "Ground", 11 I/O2 (io) "Bidirectional Port", 12 I/O3 (io) "Bidirectional Port", 13 ~{WE} (in) "Write Enable Input", 14 A5 (in) "Address Input", 15 A6 (in) "Address Input", 16 A7 (in) "Address Input", 17 A8 (in) "Address Input", 18 A9 (in) "Address Input", 19 NC "No Connection", 20 A10 (in) "Address Input", 21 A11 (in) "Address Input", 22 A12 (in) "Address Input", 23 A13 (in) "Address Input", 24 A14 (in) "Address Input", 25 I/O4 (io) "Bidirectional Port", 26 I/O5 (io) "Bidirectional Port", 27 VDD (power) "Power", 28 GND (power) "Ground", 29 I/O6 (io) "Bidirectional Port", 30 I/O7 (io) "Bidirectional Port", 31 ~{OE} (in) "Output Enable Input", 32 A15 (in) "Address Input", 33 A16 (in) "Address Input", 34 A17 (in) "Address Input", 35 A18 (in) "Address Input", 36 NC "No Connection"

## IS61WV5128EDBLL-10TI
designator U?
4 M High Speed Asynchronous CMOS SRAM with ECC, 512 K x 8, -40 to 85 degC, 44-Pin SOP (TSOP-2-44); Manufacturer: Integrated Silicon Solution Inc (ISSI); PartNumber: IS61WV5128EDBLL-10TI; Density: 4M; Organization: 512K x 8; Packing: Tray / Tube; Speed (ns): 10
footprint ISSI-TSOP-2-44_N (SOP, 44-Leads, Body 18.5x10.3mm, Pitch 0.8mm, IPC Medium Density)
part A pins: 3 A0 (in) "Address Input", 4 A1 (in) "Address Input", 5 A2 (in) "Address Input", 6 A3 (in) "Address Input", 7 A4 (in) "Address Input", 8 ~{CE} (in) "Chip Enable Input", 9 I/O0 (io) "Bidirectional Port", 10 I/O1 (io) "Bidirectional Port", 11 VDD (power) "Power", 12 GND (power) "Ground", 13 I/O2 (io) "Bidirectional Port", 14 I/O3 (io) "Bidirectional Port", 15 ~{WE} (in) "Write Enable Input", 16 A5 (in) "Address Input", 17 A6 (in) "Address Input", 18 A7 (in) "Address Input", 19 A8 (in) "Address Input", 20 A9 (in) "Address Input", 26 A10 (in) "Address Input", 27 A11 (in) "Address Input", 28 A12 (in) "Address Input", 29 A13 (in) "Address Input", 30 A14 (in) "Address Input", 31 I/O4 (io) "Bidirectional Port", 32 I/O5 (io) "Bidirectional Port", 33 VDD (power) "Power", 34 GND (power) "Ground", 35 I/O6 (io) "Bidirectional Port", 36 I/O7 (io) "Bidirectional Port", 37 ~{OE} (in) "Output Enable Input", 38 A15 (in) "Address Input", 39 A16 (in) "Address Input", 40 A17 (in) "Address Input", 41 A18 (in) "Address Input"
part B pins: 1 NC "No Connection", 2 NC "No Connection", 21 NC "No Connection", 22 NC "No Connection", 23 NC "No Connection", 24 NC "No Connection", 25 NC "No Connection", 42 NC "No Connection", 43 NC "No Connection", 44 NC "No Connection"

## IS61WV5128EDBLL-10TI-TR
designator U?
4 M High Speed Asynchronous CMOS SRAM with ECC, 512 K x 8, -40 to 85 degC, 44-Pin SOP (TSOP-2-44); Manufacturer: Integrated Silicon Solution Inc (ISSI); PartNumber: IS61WV5128EDBLL-10TI-TR; Density: 4M; Organization: 512K x 8; Packing: Tape & Reel; Speed (ns): 10
footprint ISSI-TSOP-2-44_N (SOP, 44-Leads, Body 18.5x10.3mm, Pitch 0.8mm, IPC Medium Density)
part A pins: 3 A0 (in) "Address Input", 4 A1 (in) "Address Input", 5 A2 (in) "Address Input", 6 A3 (in) "Address Input", 7 A4 (in) "Address Input", 8 ~{CE} (in) "Chip Enable Input", 9 I/O0 (io) "Bidirectional Port", 10 I/O1 (io) "Bidirectional Port", 11 VDD (power) "Power", 12 GND (power) "Ground", 13 I/O2 (io) "Bidirectional Port", 14 I/O3 (io) "Bidirectional Port", 15 ~{WE} (in) "Write Enable Input", 16 A5 (in) "Address Input", 17 A6 (in) "Address Input", 18 A7 (in) "Address Input", 19 A8 (in) "Address Input", 20 A9 (in) "Address Input", 26 A10 (in) "Address Input", 27 A11 (in) "Address Input", 28 A12 (in) "Address Input", 29 A13 (in) "Address Input", 30 A14 (in) "Address Input", 31 I/O4 (io) "Bidirectional Port", 32 I/O5 (io) "Bidirectional Port", 33 VDD (power) "Power", 34 GND (power) "Ground", 35 I/O6 (io) "Bidirectional Port", 36 I/O7 (io) "Bidirectional Port", 37 ~{OE} (in) "Output Enable Input", 38 A15 (in) "Address Input", 39 A16 (in) "Address Input", 40 A17 (in) "Address Input", 41 A18 (in) "Address Input"
part B pins: 1 NC "No Connection", 2 NC "No Connection", 21 NC "No Connection", 22 NC "No Connection", 23 NC "No Connection", 24 NC "No Connection", 25 NC "No Connection", 42 NC "No Connection", 43 NC "No Connection", 44 NC "No Connection"

## IS61WV5128EDBLL-10TLI
designator U?
4 M High Speed Asynchronous CMOS SRAM with ECC, 512 K x 8, -40 to 85 degC, 44-Pin SOP (TSOP-2-44), Pb-Free; Manufacturer: Integrated Silicon Solution Inc (ISSI); PartNumber: IS61WV5128EDBLL-10TLI; Density: 4M; Organization: 512K x 8; Packing: Tray / Tube; Speed (ns): 10
footprint ISSI-TSOP-2-44_N (SOP, 44-Leads, Body 18.5x10.3mm, Pitch 0.8mm, IPC Medium Density)
part A pins: 3 A0 (in) "Address Input", 4 A1 (in) "Address Input", 5 A2 (in) "Address Input", 6 A3 (in) "Address Input", 7 A4 (in) "Address Input", 8 ~{CE} (in) "Chip Enable Input", 9 I/O0 (io) "Bidirectional Port", 10 I/O1 (io) "Bidirectional Port", 11 VDD (power) "Power", 12 GND (power) "Ground", 13 I/O2 (io) "Bidirectional Port", 14 I/O3 (io) "Bidirectional Port", 15 ~{WE} (in) "Write Enable Input", 16 A5 (in) "Address Input", 17 A6 (in) "Address Input", 18 A7 (in) "Address Input", 19 A8 (in) "Address Input", 20 A9 (in) "Address Input", 26 A10 (in) "Address Input", 27 A11 (in) "Address Input", 28 A12 (in) "Address Input", 29 A13 (in) "Address Input", 30 A14 (in) "Address Input", 31 I/O4 (io) "Bidirectional Port", 32 I/O5 (io) "Bidirectional Port", 33 VDD (power) "Power", 34 GND (power) "Ground", 35 I/O6 (io) "Bidirectional Port", 36 I/O7 (io) "Bidirectional Port", 37 ~{OE} (in) "Output Enable Input", 38 A15 (in) "Address Input", 39 A16 (in) "Address Input", 40 A17 (in) "Address Input", 41 A18 (in) "Address Input"
part B pins: 1 NC "No Connection", 2 NC "No Connection", 21 NC "No Connection", 22 NC "No Connection", 23 NC "No Connection", 24 NC "No Connection", 25 NC "No Connection", 42 NC "No Connection", 43 NC "No Connection", 44 NC "No Connection"

## IS61WV5128EDBLL-10TLI-TR
designator U?
4 M High Speed Asynchronous CMOS SRAM with ECC, 512 K x 8, -40 to 85 degC, 44-Pin SOP (TSOP-2-44), Pb-Free; Manufacturer: Integrated Silicon Solution Inc (ISSI); PartNumber: IS61WV5128EDBLL-10TLI-TR; Density: 4M; Organization: 512K x 8; Packing: Tape & Reel; Speed (ns): 10
footprint ISSI-TSOP-2-44_N (SOP, 44-Leads, Body 18.5x10.3mm, Pitch 0.8mm, IPC Medium Density)
part A pins: 3 A0 (in) "Address Input", 4 A1 (in) "Address Input", 5 A2 (in) "Address Input", 6 A3 (in) "Address Input", 7 A4 (in) "Address Input", 8 ~{CE} (in) "Chip Enable Input", 9 I/O0 (io) "Bidirectional Port", 10 I/O1 (io) "Bidirectional Port", 11 VDD (power) "Power", 12 GND (power) "Ground", 13 I/O2 (io) "Bidirectional Port", 14 I/O3 (io) "Bidirectional Port", 15 ~{WE} (in) "Write Enable Input", 16 A5 (in) "Address Input", 17 A6 (in) "Address Input", 18 A7 (in) "Address Input", 19 A8 (in) "Address Input", 20 A9 (in) "Address Input", 26 A10 (in) "Address Input", 27 A11 (in) "Address Input", 28 A12 (in) "Address Input", 29 A13 (in) "Address Input", 30 A14 (in) "Address Input", 31 I/O4 (io) "Bidirectional Port", 32 I/O5 (io) "Bidirectional Port", 33 VDD (power) "Power", 34 GND (power) "Ground", 35 I/O6 (io) "Bidirectional Port", 36 I/O7 (io) "Bidirectional Port", 37 ~{OE} (in) "Output Enable Input", 38 A15 (in) "Address Input", 39 A16 (in) "Address Input", 40 A17 (in) "Address Input", 41 A18 (in) "Address Input"
part B pins: 1 NC "No Connection", 2 NC "No Connection", 21 NC "No Connection", 22 NC "No Connection", 23 NC "No Connection", 24 NC "No Connection", 25 NC "No Connection", 42 NC "No Connection", 43 NC "No Connection", 44 NC "No Connection"

## IS61WV6416DBLL-8BI
designator U?
1 M High Speed Asynchronous CMOS SRAM, 64 K x 16, -40 to 85 degC, 48-Pin BGA (TF-BGA-48); Manufacturer: Integrated Silicon Solution Inc (ISSI); PartNumber: IS61WV6416DBLL-8BI; Density: 1M; Organization: 64K x 16; Packing: Tray / Tube; Speed (ns): 8
footprint ISSI-TF-BGA-48-6000X8000DE (BGA, 48-Balls, Body 8x6mm, Pitch 0.75mm)
part A pins: A1 ~{LB} (in) "Lower-byte Control (I/O0-I/O7)", A2 ~{OE} (in) "Output Enable Input", A3 A0 (in) "Address Input", A4 A1 (in) "Address Input", A5 A2 (in) "Address Input", B1 I/O8 (io) "Data Input/Output", B2 ~{UB} (in) "Upper-byte Control (I/O8-I/O15)", B3 A3 (in) "Address Input", B4 A4 (in) "Address Input", B5 ~{CE} (in) "Chip Enable Input", B6 I/O0 (io) "Data Input/Output", C1 I/O9 (io) "Data Input/Output", C2 I/O10 (io) "Data Input/Output", C3 A5 (in) "Address Input", C4 A6 (in) "Address Input", C5 I/O1 (io) "Data Input/Output", C6 I/O2 (io) "Data Input/Output", D1 GND (power) "Ground", D2 I/O11 (io) "Data Input/Output", D4 A7 (in) "Address Input", D5 I/O3 (io) "Data Input/Output", D6 VDD (power) "Power", E1 VDD (power) "Power", E2 I/O12 (io) "Data Input/Output", E5 I/O4 (io) "Data Input/Output", E6 GND (power) "Ground", F1 I/O14 (io) "Data Input/Output", F2 I/O13 (io) "Data Input/Output", F3 A14 (in) "Address Input", F4 A15 (in) "Address Input", F5 I/O5 (io) "Data Input/Output", F6 I/O6 (io) "Data Input/Output", G1 I/O15 (io) "Data Input/Output", G3 A12 (in) "Address Input", G4 A13 (in) "Address Input", G5 ~{WE} (in) "Write Enable Input", G6 I/O7 (io) "Data Input/Output", H2 A8 (in) "Address Input", H3 A9 (in) "Address Input", H4 A10 (in) "Address Input", H5 A11 (in) "Address Input"
part B pins: A6 NC "No Connection", D3 NC "No Connection", E3 NC "No Connection", E4 NC "No Connection", G2 NC "No Connection", H1 NC "No Connection", H6 NC "No Connection"

## IS61WV6416DBLL-8BI-TR
designator U?
1 M High Speed Asynchronous CMOS SRAM, 64 K x 16, -40 to 85 degC, 48-Pin BGA (TF-BGA-48); Manufacturer: Integrated Silicon Solution Inc (ISSI); PartNumber: IS61WV6416DBLL-8BI-TR; Density: 1M; Organization: 64K x 16; Packing: Tape & Reel; Speed (ns): 8
footprint ISSI-TF-BGA-48-6000X8000DE (BGA, 48-Balls, Body 8x6mm, Pitch 0.75mm)
part A pins: A1 ~{LB} (in) "Lower-byte Control (I/O0-I/O7)", A2 ~{OE} (in) "Output Enable Input", A3 A0 (in) "Address Input", A4 A1 (in) "Address Input", A5 A2 (in) "Address Input", B1 I/O8 (io) "Data Input/Output", B2 ~{UB} (in) "Upper-byte Control (I/O8-I/O15)", B3 A3 (in) "Address Input", B4 A4 (in) "Address Input", B5 ~{CE} (in) "Chip Enable Input", B6 I/O0 (io) "Data Input/Output", C1 I/O9 (io) "Data Input/Output", C2 I/O10 (io) "Data Input/Output", C3 A5 (in) "Address Input", C4 A6 (in) "Address Input", C5 I/O1 (io) "Data Input/Output", C6 I/O2 (io) "Data Input/Output", D1 GND (power) "Ground", D2 I/O11 (io) "Data Input/Output", D4 A7 (in) "Address Input", D5 I/O3 (io) "Data Input/Output", D6 VDD (power) "Power", E1 VDD (power) "Power", E2 I/O12 (io) "Data Input/Output", E5 I/O4 (io) "Data Input/Output", E6 GND (power) "Ground", F1 I/O14 (io) "Data Input/Output", F2 I/O13 (io) "Data Input/Output", F3 A14 (in) "Address Input", F4 A15 (in) "Address Input", F5 I/O5 (io) "Data Input/Output", F6 I/O6 (io) "Data Input/Output", G1 I/O15 (io) "Data Input/Output", G3 A12 (in) "Address Input", G4 A13 (in) "Address Input", G5 ~{WE} (in) "Write Enable Input", G6 I/O7 (io) "Data Input/Output", H2 A8 (in) "Address Input", H3 A9 (in) "Address Input", H4 A10 (in) "Address Input", H5 A11 (in) "Address Input"
part B pins: A6 NC "No Connection", D3 NC "No Connection", E3 NC "No Connection", E4 NC "No Connection", G2 NC "No Connection", H1 NC "No Connection", H6 NC "No Connection"

## IS61WV6416DBLL-8BLI
designator U?
1 M High Speed Asynchronous CMOS SRAM, 64 K x 16, -40 to 85 degC, 48-Pin BGA (TF-BGA-48), Pb-Free; Manufacturer: Integrated Silicon Solution Inc (ISSI); PartNumber: IS61WV6416DBLL-8BLI; Density: 1M; Organization: 64K x 16; Packing: Tray / Tube; Speed (ns): 8
footprint ISSI-TF-BGA-48-6000X8000DE (BGA, 48-Balls, Body 8x6mm, Pitch 0.75mm)
part A pins: A1 ~{LB} (in) "Lower-byte Control (I/O0-I/O7)", A2 ~{OE} (in) "Output Enable Input", A3 A0 (in) "Address Input", A4 A1 (in) "Address Input", A5 A2 (in) "Address Input", B1 I/O8 (io) "Data Input/Output", B2 ~{UB} (in) "Upper-byte Control (I/O8-I/O15)", B3 A3 (in) "Address Input", B4 A4 (in) "Address Input", B5 ~{CE} (in) "Chip Enable Input", B6 I/O0 (io) "Data Input/Output", C1 I/O9 (io) "Data Input/Output", C2 I/O10 (io) "Data Input/Output", C3 A5 (in) "Address Input", C4 A6 (in) "Address Input", C5 I/O1 (io) "Data Input/Output", C6 I/O2 (io) "Data Input/Output", D1 GND (power) "Ground", D2 I/O11 (io) "Data Input/Output", D4 A7 (in) "Address Input", D5 I/O3 (io) "Data Input/Output", D6 VDD (power) "Power", E1 VDD (power) "Power", E2 I/O12 (io) "Data Input/Output", E5 I/O4 (io) "Data Input/Output", E6 GND (power) "Ground", F1 I/O14 (io) "Data Input/Output", F2 I/O13 (io) "Data Input/Output", F3 A14 (in) "Address Input", F4 A15 (in) "Address Input", F5 I/O5 (io) "Data Input/Output", F6 I/O6 (io) "Data Input/Output", G1 I/O15 (io) "Data Input/Output", G3 A12 (in) "Address Input", G4 A13 (in) "Address Input", G5 ~{WE} (in) "Write Enable Input", G6 I/O7 (io) "Data Input/Output", H2 A8 (in) "Address Input", H3 A9 (in) "Address Input", H4 A10 (in) "Address Input", H5 A11 (in) "Address Input"
part B pins: A6 NC "No Connection", D3 NC "No Connection", E3 NC "No Connection", E4 NC "No Connection", G2 NC "No Connection", H1 NC "No Connection", H6 NC "No Connection"

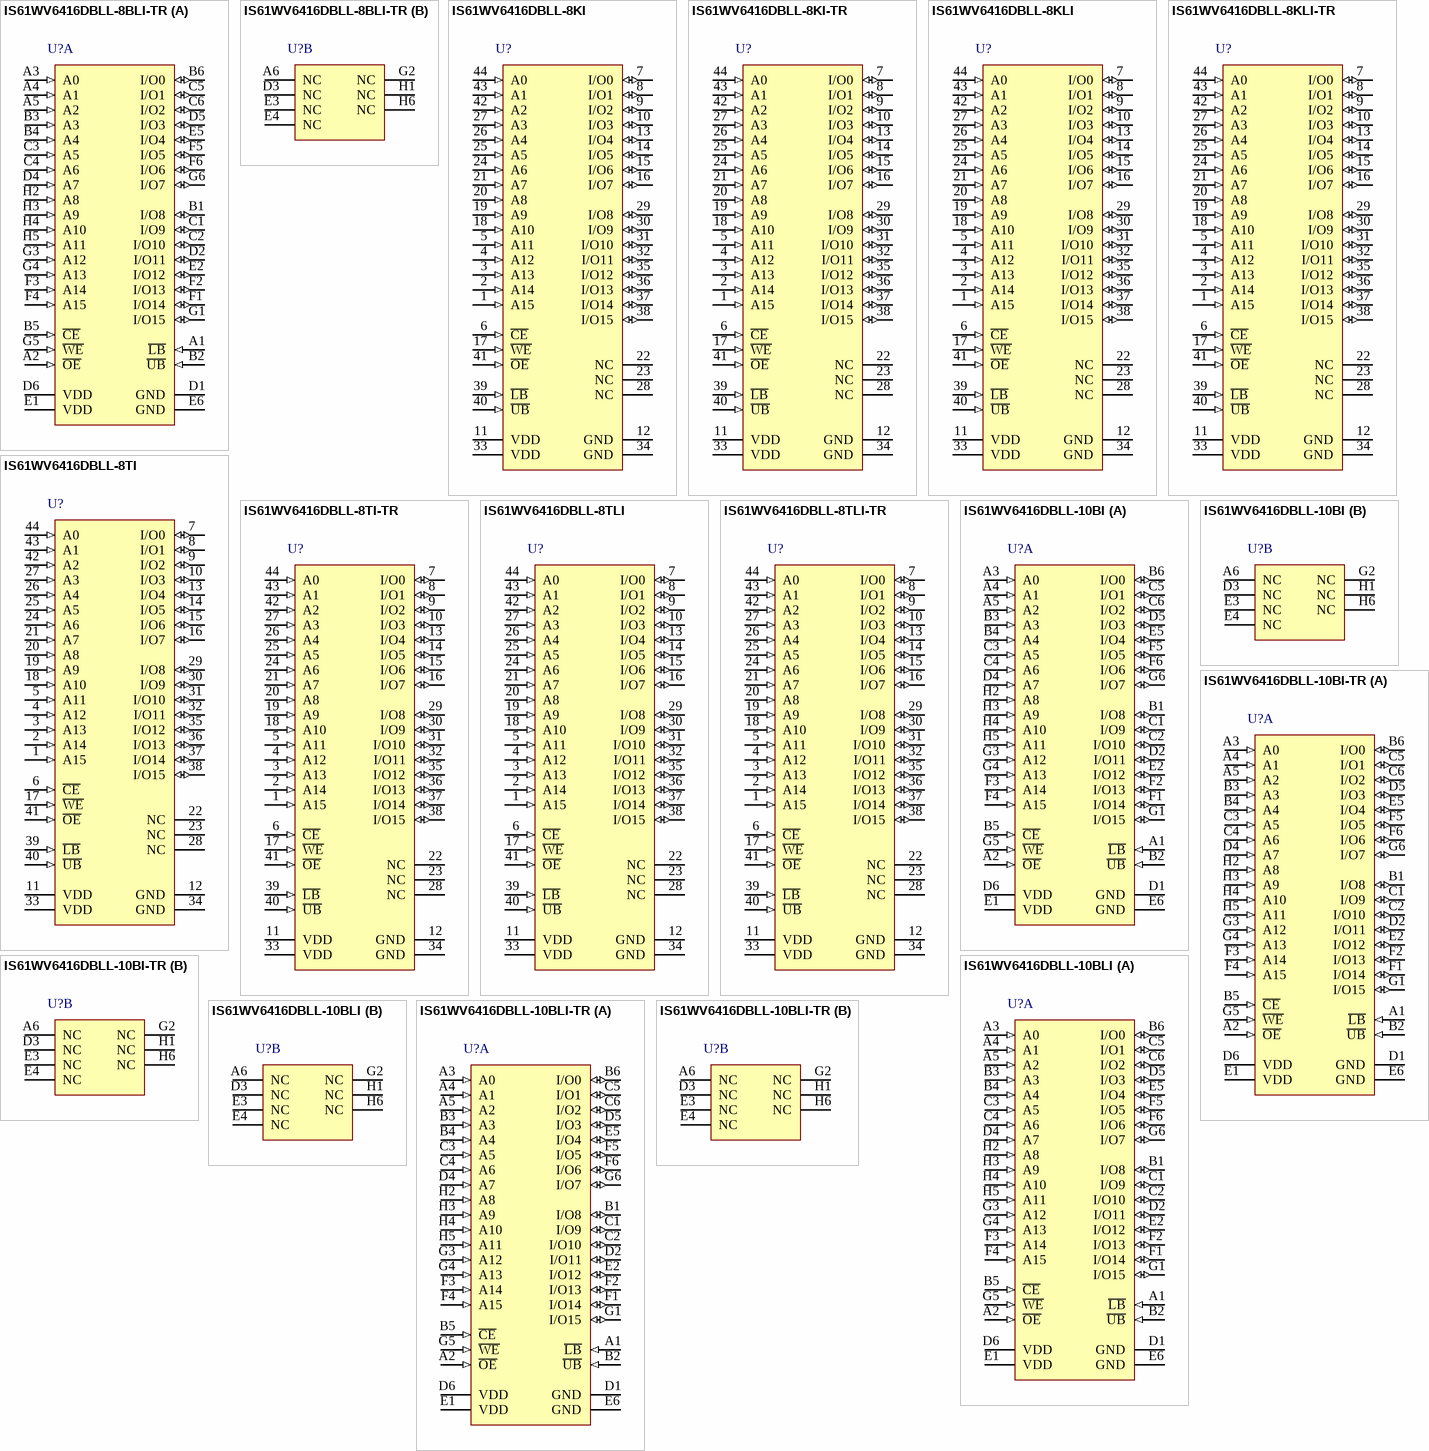
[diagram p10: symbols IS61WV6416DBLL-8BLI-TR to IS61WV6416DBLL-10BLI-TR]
